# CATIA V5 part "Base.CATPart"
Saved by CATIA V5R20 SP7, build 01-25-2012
Part number: Base
Bounding box of the stored display mesh (mm): x -90 to 90, y -70 to 210, z -70 to 20
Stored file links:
  D:\IFMA\COURS\2A\projet balance IAO\catia\Base.CATPart
  D:\IFMA\COURS\2A\projet balance IAO\catia\Ass_projet_balance.CATProduct
  D:\IFMA\COURS\2A\projet balance IAO\catia\Barre_HEG.CATPart
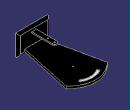
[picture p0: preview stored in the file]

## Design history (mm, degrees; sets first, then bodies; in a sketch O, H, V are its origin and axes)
Set1
  Plane1 "Plan_socle_1": linked copy from another document
  Point1 "Point.E": linked copy from another document
  Plane2 "Plan_socle_2": linked copy from another document
  Point2 "Point.C": linked copy from another document
  Plane3: linked copy from another document
  Point3 "Point.D": linked copy from another document
  Point4 "Point.J": linked copy from another document
Body1 (main body)
  Sketch1 on Plane1, origin (0, -60, 0), H (-1, 0, 0), V (0, 0, 1)
    line L1 (-70, 20) -> (70, 20)
    line L2 (70, 20) -> (70, -70)
    line L3 (70, -70) -> (-70, -70)
    line L4 (-70, -70) -> (-70, 20)
    reference projected point E1 (0, 0) from Point1
    reference projected point E2 (0, 0) from Point1
    distance L1 L3 = 90
    distance L2 L4 = 140
    distance L3 E1 = 70
    distance L2 E2 = 70
    horizontal: L1 H, L3 H
    vertical: L2 V, L4 V
  Pad1: profile Sketch1, direction (0, -1, 0), length 10
  Sketch2 on Plane2, origin (0, 0, -50), H (1, 0, 0), V (0, 1, 0)
    line L1 (-40, -60) -> (-90, 170)
    point P1 (-40, -60)
    point P2 (-90, 170)
    line L2 (40, -60) -> (90, 170)
    point P3 (40, -60)
    point P4 (90, 170)
    spline S1 through (90, 170) (0, 210) (-90, 170)
    reference projected point E1 (0, 110) from Point2
    reference projected point E2 (0, 110) from Point2
    reference projected point E3 (0, 110) from Point2
    reference projected point E4 (0, 110) from Point2
    reference projected point E5 (0, 110) from Point2
    line L3 (40, -60) -> (-40, -60)
    reference projected point E6 (0, 0) from Point1
    reference projected point E7 (0, 0) from Point1
    reference projected point E8 (0, 0) from Point1
    point P5 (90, 170)
    point P6 (0, 210)
    point P7 (-90, 170)
    distance P5 E1 H = 90
    distance P5 E2 V = 60
    distance P6 E3 V = 100
    distance P7 E4 H = 90
    distance P7 E5 V = 60
    distance L3 E6 = 60
    distance P3 E7 H = 40
    distance P1 E8 H = 40
    coincidence: P5 P4, P6 V, P7 P2
    horizontal: L3 H
  Pad2: profile Sketch2, direction (0, 0, -1), length 10
  Sketch3 on start face of Pad2, origin (0, 0, -50), H (1, 0, 0), V (0, 1, 0)
    arc A1 centre (0, 110) radius 85 from (44.7, 182.2974) to (-44.7923, 182.2402) ccw
    point P1 (0, 110)
    point P2 (44.7, 182.2974)
    arc A2 centre (0, 110) radius 75 from (39, 174.0625) to (-39, 174.0625) ccw
    point P4 (39, 174.0625)
    point P5 (-39, 174.0625)
    line L1 (44.7, 182.2974) -> (39, 174.0625)
    line L2 (-44.7923, 182.2402) -> (-39, 174.0625)
    reference projected point E1 (0, 110) from Point2
    reference projected point E2 (0, 190) from Point4
    reference projected point E3 (0, 190) from Point4
    radius A2 = 75
    radius A1 = 85
    angle L1 L2 = 70
    distance P4 E2 H = 39
    distance P5 E3 H = 39
    distance P2 P4 H = 5.7
    coincidence: P1 V, P1 E1
  Pocket1: profile Sketch3, direction (0, 0, -1), length 1
  Sketch4 on Plane3, origin (0, 0, 0), H (1, 0, 0), V (0, 1, 0)
    arc A1 centre (0, 30) radius 10 from (10, 30) to (-10, 30) ccw
    point P1 (0, 30)
    line L1 (10, 30) -> (10, -60)
    line L2 (-10, 30) -> (-10, -60)
    line L3 (-10, -60) -> (10, -60)
    reference projected point E1 (0, 30) from Point3
    reference intersected line E2 through (0, -60) direction (-1, 0) from Plane1
    distance L1 L2 = 20
    coincidence: P1 V, P1 E1, L3 E2
    vertical: L1 V
    tangency: L2 A1, A1 L1
    horizontal: L3 H
  Pad3: profile Sketch4, direction (0, 0, -1), length 5
  Sketch5 on start face of Pad3, origin (0, 0, 0), H (1, 0, 0), V (0, 1, 0)
    circle A1 centre (0, 30) radius 2.5
    point P1 (0, 30)
    circle A2 centre (0, 0) radius 2.5
    point P2 (0, 0)
    reference projected point E1 (0, 30) from Point3
    reference projected point E2 (0, 0) from Point1
    radius A2 = 2.5
    radius A1 = 2.5
    coincidence: P1 E1, P2 E2
  Pocket2: profile Sketch5, direction (0, 0, -1), through (limit type 6)
  Fillet1: radius 10, on edge [face of Pad1 from Sketch1.L2 | start face of Pad1]; edge [face of Pad1 from Sketch1.L3 | start face of Pad1]; edge [face of Pad1 from Sketch1.L4 | start face of Pad1]; edge [face of Pad1 from Sketch1.L1 | start face of Pad1]
  Sketch6 on start face of Pad2, origin (0, 0, -50), H (1, 0, 0), V (0, 1, 0)
    circle A1 centre (0, 110) radius 2.5
    point P1 (0, 110)
    reference projected point E1 (0, 110) from Point2
    radius A1 = 2.5
    coincidence: P1 E1
  Pocket3: profile Sketch6, direction (0, 0, -1), through (limit type 6)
